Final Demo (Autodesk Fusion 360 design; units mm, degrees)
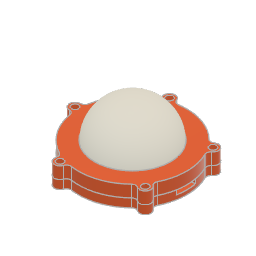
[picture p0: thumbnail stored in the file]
sketch "Sketch1" plane through (0, 0, 0) normal (0, 1, 0) x axis (1, 0, 0)
  line L1 (0, 45) -> (0, 0)
  line L2 (0, -35) -> (0, 0)
  circle C1 centre (0, 0) radius 15
  circle C2 centre (0, 0) radius 17.5
  circle C3 centre (0, 0) radius 22.5
  point P1 (0, 0)
  point P2 (0, 0)
  point P4 (0, 0)
  point P6 (0, 0)
  coincident P1 P2
  concentric C1 C2
  coincident P1 P4
  vertical L1
  coincident P2 P6
  parallel L1 L2
  concentric C2 C3
  dimension "d1" diameter C1 = 30
  dimension "d2" diameter C2 = 35
  dimension "d4" diameter C3 = 45
revolve "Revolve1" sketch "Sketch1" AlongAngle 180 bodies "Membrane"
extrude "Extrude1" add blind -5
move "Move1"
sketch "Sketch2" plane through (0, 0, 0) normal (0, 1, 0) x axis (1, 0, 0)
  line L1 (25, 25) -> (-25, 25)
  line L2 (25, -25) -> (25, 25)
  line L3 (-25, -25) -> (25, -25)
  line L4 (-25, 25) -> (-25, -25)
  circle C1 centre (0, 0) radius 22.5
  point P1 (0, 0)
  point P2 (0, 0)
  coincident P1 P2
  horizontal L1
  vertical L2
  horizontal L3
  vertical L4
  dimension "d7" diameter C1 = 45
extrude "Extrude2" new body sketch "Sketch2" along normal blind 3.5 bodies "Cap"
sketch "Sketch3" plane through (0, 3.5, 0) normal (0, 1, 0) x axis (-1, 0, 0)
  line L1 (-25, 25) -> (25, 25)
  line L2 (-25, -25) -> (-25, 25)
  line L3 (25, -25) -> (-25, -25)
  line L4 (25, 25) -> (25, -25)
  circle C1 centre (0, 0) radius 22.5
  circle C2 centre (0, 0) radius 17.5
  concentric C1 C2
  dimension "d10" diameter C2 = 35
extrude "Extrude3" add sketch "Sketch3" along normal blind 2
extrude "Extrude4" new body sketch "Sketch2" against normal blind 8
sketch "Sketch4" plane through (0, 0, 0) normal (0, 1, 0) x axis (-1, 0, 0)
  line L1 (-25, 25) -> (25, 25)
  line L2 (-25, -25) -> (-25, 25)
  line L3 (25, -25) -> (-25, -25)
  line L4 (25, 25) -> (25, -25)
  line L5 (-6, -0.9751) -> (-25, -0.9751)
  line L6 (0, 1.0068) -> (0, -0.9751)
  line L7 (-25, 1.0068) -> (-6, 1.0068)
  line L8 (0, 8) -> (0, 0)
  line L9 (5.4, 8) -> (-6, 8)
  line L10 (5.4, -8) -> (5.4, 8)
  line L11 (-6, -8) -> (5.4, -8)
  line L12 (-6, -0.9751) -> (-6, -8)
  line L13 (-6, 8) -> (-6, 1.0068)
  circle C1 centre (0, 0) radius 17.5
  circle C2 centre (0, 0) radius 20
  point P6 (-25, -0.9751)
  point P9 (-25, 1.0068)
  point P1 (0, 0)
  point P10 (0, 0)
  point P16 (-6, 1.0068)
  point P18 (0, 0)
  point P19 (0, 0)
  point P11 (0, 8)
  point P12 (-6, 8)
  point P13 (5.4, 8)
  coincident L2 P6
  perpendicular L2 L5
  perpendicular L5 L6
  coincident L2 P9
  perpendicular L2 L7
  coincident P1 P10
  parallel L6 L8
  horizontal L9
  vertical L10
  horizontal L11
  vertical L12
  coincident P16 L12
  collinear L12 L13
  coincident P1 P18
  coincident P10 P19
  dimension "d17" distance P10 P11 = 8
  dimension "d18" distance P12 P13 = 11.4
  dimension "d19" distance L2 L13 = 19
  dimension "d20" diameter C1 = 35
  dimension "d23" diameter C2 = 40
extrude "Extrude6" cut sketch "Sketch4" profile of L2 L5 L7 L9 L10 L11 L13 C1 C2 against normal blind 1
sketch "Sketch5" plane through (0, 5.5, 0) normal (0, 1, 0) x axis (-1, 0, 0)
  line L1 (25, 25) -> (25, -25)
  line L2 (-25, 25) -> (25, 25)
  line L3 (-25, -25) -> (-25, 25)
  line L4 (25, -25) -> (-25, -25)
  line L5 (-25, 25) -> (25, -25)
  line L6 (25, 25) -> (-25, -25)
  line L7 (-20, -20) -> (20, -20)
  line L8 (-20, 20) -> (-20, -20)
  line L9 (20, 20) -> (-20, 20)
  line L10 (20, -20) -> (20, 20)
  circle C1 centre (0, 0) radius 17.5
  point P3 (25, -25)
  point P7 (25, -25)
  point P5 (-25, 25)
  point P8 (-25, 25)
  point P6 (-25, -25)
  point P9 (-25, -25)
  point P4 (25, 25)
  point P10 (25, 25)
  point P13 (-20, 20)
  point P11 (20, -20)
  coincident P3 P7
  coincident P5 P8
  coincident P6 P9
  coincident P4 P10
  horizontal L7
  vertical L8
  horizontal L9
  vertical L10
  coincident L5 P13
  coincident L5 P11
sketch "Sketch6" plane through (0, -8, 0) normal (0, -1, 0) x axis (1, 0, 0)
  line L1 (-25, 25) -> (25, 25)
  line L2 (-25, -25) -> (-25, 25)
  line L3 (25, -25) -> (-25, -25)
  line L4 (25, 25) -> (25, -25)
  line L5 (-18.35, 22.6847) -> (-16.8, 20)
  line L6 (-21.45, 22.6847) -> (-18.35, 22.6847)
  line L7 (-23, 20) -> (-21.45, 22.6847)
  line L8 (-21.45, 17.3153) -> (-23, 20)
  line L9 (-18.35, 17.3153) -> (-21.45, 17.3153)
  line L10 (-16.8, 20) -> (-18.35, 17.3153)
  line L11 (21.65, 22.6847) -> (23.2, 20)
  line L12 (18.55, 22.6847) -> (21.65, 22.6847)
  line L13 (17, 20) -> (18.55, 22.6847)
  line L14 (18.55, 17.3153) -> (17, 20)
  line L15 (21.65, 17.3153) -> (18.55, 17.3153)
  line L16 (23.2, 20) -> (21.65, 17.3153)
  line L17 (-22.6847, -18.45) -> (-20, -16.9)
  line L18 (-22.6847, -21.55) -> (-22.6847, -18.45)
  line L19 (-20, -23.1) -> (-22.6847, -21.55)
  line L20 (-17.3153, -21.55) -> (-20, -23.1)
  line L21 (-17.3153, -18.45) -> (-17.3153, -21.55)
  line L22 (-20, -16.9) -> (-17.3153, -18.45)
  line L23 (17.3153, -18.45) -> (20, -16.9)
  line L24 (17.3153, -21.55) -> (17.3153, -18.45)
  line L25 (20, -23.1) -> (17.3153, -21.55)
  line L26 (22.6847, -21.55) -> (20, -23.1)
  line L27 (22.6847, -18.45) -> (22.6847, -21.55)
  line L28 (20, -16.9) -> (22.6847, -18.45)
  point P6 (-16.8, 20)
  point P12 (-19.9, 20)
  point P13 (23.2, 20)
  point P19 (20.1, 20)
  point P20 (-20, -16.9)
  point P26 (-20, -20)
  point P27 (20, -16.9)
  point P33 (20, -20)
  dimension "d24" distance P6 P12 = 3.1
  dimension "d25" distance P13 P19 = 3.1
  dimension "d26" distance P20 P26 = 3.1
  dimension "d27" distance P27 P33 = 3.1
extrude "Extrude7" cut sketch "Sketch6" profile of L5 L6 L7 L8 L9 L10 L11 L12 L13 L14 L15 L16 L17 L18 L19 L20 L21 L22 L23 L24 L25 L26 L27 L28 against normal blind 2.8
hole "Hole1" HoleDepth 12 HoleDiameter 3.2 TipAngle 180
extrude "Extrude8" cut sketch "Sketch4" profile of L5 L7 C1 C2 against normal blind 0.5
sketch "Sketch7" plane through (0, 0, 0) normal (0, 1, 0) x axis (1, 0, 0)
  line L1 (25, 25) -> (-25, 25)
  line L2 (25, -25) -> (25, 25)
  line L3 (-25, -25) -> (25, -25)
  line L4 (-25, 25) -> (-25, -25)
  horizontal L1
  vertical L2
  horizontal L3
  vertical L4
combine "Combine1"
sketch "Sketch8" plane through (0, 0, 0) normal (0, -1, 0) x axis (1, 0, 0)
  line L1 (25, 25) -> (-25, 25)
  line L2 (25, -25) -> (25, 25)
  line L3 (-25, -25) -> (25, -25)
  line L4 (-25, 25) -> (-25, -25)
  circle C1 centre (0, 0) radius 15
  circle C2 centre (0, 0) radius 22.5
  circle C3 centre (-0.0783, 18.7498) radius 3.75
  circle C4 centre (-0.0153, -20.25) radius 2.25
  point P1 (0, 0)
  point P7 (0, 0)
  horizontal L1
  vertical L2
  horizontal L3
  vertical L4
  coincident P1 P7
  tangent C1 C3
  dimension "d39" diameter C2 = 45
extrude "Extrude1" add sketch "Sketch8" profile of C1 L1 L2 L3 L4 along normal blind 5
extrude "Extrude2" cut sketch "Sketch8" profile of C2 C3 C4 along normal blind 10
sketch "Sketch9" plane through (0, -5, 0) normal (0, -1, 0) x axis (1, 0, 0)
  line L1 (25, -25) -> (-25, -25)
  line L2 (25, 25) -> (25, -25)
  line L3 (-25, 25) -> (25, 25)
  line L4 (-25, -25) -> (-25, 25)
  line L5 (25, -25) -> (-25, 25)
  line L6 (-25, -25) -> (25, 25)
  line L7 (21, 21) -> (-21, 21)
  line L8 (21, -21) -> (21, 21)
  line L9 (-21, -21) -> (21, -21)
  line L10 (-21, 21) -> (-21, -21)
  circle C1 centre (-0.0783, 18.7498) radius 3.75
  arc A1 centre (0, 0) radius 22.5 clockwise from (-0.0034, -22.5) to (-0.0307, -22.5)
  arc A2 centre (-0.0153, -20.25) radius 2.25 clockwise from (-0.0307, -22.5) to (-0.0034, -22.5)
  circle C2 centre (0, 0) radius 22.5
  point P1 (0, 0)
  point P11 (0, 0)
  point P10 (-25, 25)
  point P12 (-25, 25)
  point P8 (25, -25)
  point P13 (25, -25)
  point P9 (25, 25)
  point P14 (25, 25)
  point P7 (-25, -25)
  point P15 (-25, -25)
  point P18 (21, -21)
  point P16 (-21, 21)
  coincident P1 P11
  tangent C1 C2
  coincident P10 P12
  coincident P8 P13
  coincident P9 P14
  coincident P7 P15
  horizontal L7
  vertical L8
  horizontal L9
  vertical L10
  coincident L5 P18
  coincident L5 P16
hole "Hole1" HoleDepth 31 HoleDiameter 3.2 TipAngle 180
sketch "Sketch10" plane through (0, 25, 0) normal (0, 1, 0) x axis (-1, 0, 0)
  line L1 (-25, 25) -> (25, 25)
  line L2 (-25, -25) -> (-25, 25)
  line L3 (25, -25) -> (-25, -25)
  line L4 (25, 25) -> (25, -25)
  line L5 (23.6847, -22.55) -> (21, -24.1)
  line L6 (23.6847, -19.45) -> (23.6847, -22.55)
  line L7 (21, -17.9) -> (23.6847, -19.45)
  line L8 (18.3153, -19.45) -> (21, -17.9)
  line L9 (18.3153, -22.55) -> (18.3153, -19.45)
  line L10 (21, -24.1) -> (18.3153, -22.55)
  line L11 (-18.3153, -22.55) -> (-21, -24.1)
  line L12 (-18.3153, -19.45) -> (-18.3153, -22.55)
  line L13 (-21, -17.9) -> (-18.3153, -19.45)
  line L14 (-23.6847, -19.45) -> (-21, -17.9)
  line L15 (-23.6847, -22.55) -> (-23.6847, -19.45)
  line L16 (-21, -24.1) -> (-23.6847, -22.55)
  line L17 (-18.3153, 19.45) -> (-21, 17.9)
  line L18 (-18.3153, 22.55) -> (-18.3153, 19.45)
  line L19 (-21, 24.1) -> (-18.3153, 22.55)
  line L20 (-23.6847, 22.55) -> (-21, 24.1)
  line L21 (-23.6847, 19.45) -> (-23.6847, 22.55)
  line L22 (-21, 17.9) -> (-23.6847, 19.45)
  line L23 (23.6847, 19.45) -> (21, 17.9)
  line L24 (23.6847, 22.55) -> (23.6847, 19.45)
  line L25 (21, 24.1) -> (23.6847, 22.55)
  line L26 (18.3153, 22.55) -> (21, 24.1)
  line L27 (18.3153, 19.45) -> (18.3153, 22.55)
  line L28 (21, 17.9) -> (18.3153, 19.45)
  circle C1 centre (-21, -21) radius 1.6
  circle C2 centre (21, 21) radius 1.6
  circle C3 centre (-21, 21) radius 1.6
  circle C4 centre (21, -21) radius 1.6
  point P5 (21, -21)
  point P16 (21, -21)
  point P2 (-21, -21)
  point P23 (-21, -21)
  point P4 (-21, 21)
  point P30 (-21, 21)
  point P3 (21, 21)
  point P37 (21, 21)
  point P10 (21, -24.1)
  point P17 (-21, -24.1)
  point P24 (-21, 17.9)
  point P31 (21, 17.9)
  coincident P5 P16
  coincident P2 P23
  coincident P4 P30
  coincident P3 P37
  dimension "d45" distance P10 P16 = 3.1
  dimension "d46" distance P17 P23 = 3.1
  dimension "d47" distance P24 P30 = 3.1
  dimension "d48" distance P31 P37 = 3.1
extrude "Extrude3" cut sketch "Sketch10" profile of C1 C2 C3 C4 L5 L6 L7 L8 L9 L10 L11 L12 L13 L14 L15 L16 L17 L18 L19 L20 L21 L22 L23 L24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 against normal blind 3
extrude "Extrude9" cut of existing geometry blind -1
sketch "Sketch11" plane through (0, -2, 0) normal (0, 1, 0) x axis (-1, 0, 0)
  line L1 (-25, 1.0068) -> (-17.471, 1.0068)
  line L2 (-25, -0.9751) -> (-25, 1.0068)
  line L3 (-17.4728, -0.9751) -> (-25, -0.9751)
  line L4 (-16.4984, 3) -> (-25.5767, 3)
  line L5 (-16.4984, -3.0369) -> (-16.4984, 3)
  line L6 (-25.5767, -3.0369) -> (-16.4984, -3.0369)
  line L7 (-25.5767, 3) -> (-25.5767, -3.0369)
  arc A1 centre (0, 0) radius 17.5 clockwise from (-17.471, 1.0068) to (-17.4728, -0.9751)
  horizontal L4
  vertical L5
  horizontal L6
  vertical L7
extrude "Extrude10" cut sketch "Sketch11" along normal blind 3
extrude "Extrude11" cut of existing geometry blind -4
extrude "Extrude12" cut of existing geometry blind -5
sketch "Sketch12" plane through (0, -2, 0) normal (0, 1, 0) x axis (-1, 0, 0)
  line L1 (-25, 3) -> (-17.2409, 3)
  line L2 (-25, -3.0369) -> (-25, 3)
  line L3 (-17.2345, -3.0369) -> (-25, -3.0369)
  line L4 (-16, 3) -> (-17.2409, 3)
  line L5 (-15.993, -3.0369) -> (-17.2345, -3.0369)
  arc A1 centre (0, 0) radius 17.5 clockwise from (-17.2409, 3) to (-17.2345, -3.0369)
  circle C1 centre (0, 0) radius 16.2788
  point P2 (-17.2409, 3)
  point P8 (-17.2409, 3)
  point P9 (-16, 3)
  point P5 (-17.2345, -3.0369)
  point P10 (-17.2345, -3.0369)
  point P11 (-15.993, -3.0369)
  concentric A1 C1
  coincident P2 P8
  coincident C1 P9
  parallel L1 L4
  coincident P5 P10
  coincident C1 P11
  parallel L3 L5
extrude "Extrude13" add sketch "Sketch12" profile of A1 C1 L4 L5 along normal blind 1
offset_faces "OffsetFaces1" distance -1
extrude "Extrude14" add of existing geometry blind 0.5
extrude "Extrude15" add of existing geometry blind 0.5
offset_faces "OffsetFaces2" distance 1
sketch "Sketch13" plane through (0, 5.5, 0) normal (0, 1, 0) x axis (-1, 0, 0)
  line L1 (25, 25) -> (25, -25)
  line L2 (-25, 25) -> (25, 25)
  line L3 (-25, -25) -> (-25, 25)
  line L4 (25, -25) -> (-25, -25)
  circle C1 centre (-20, 20) radius 1.6
  circle C2 centre (20, -20) radius 1.6
  circle C3 centre (-20, -20) radius 1.6
  circle C4 centre (20, 20) radius 1.6
  circle C5 centre (0, 0) radius 17.5
  circle C6 centre (0, 0) radius 22.5
  circle C7 centre (0, 0) radius 25
  point P1 (0, 0)
  point P11 (0, 0)
  coincident P1 P11
  concentric C5 C7
  tangent L2 C7
  dimension "d67" diameter C6 = 45
extrude "Extrude16" cut sketch "Sketch13" profile of C1 C2 C3 C4 L1 L2 L3 L4 C7 against normal blind 23
sketch "Sketch14" plane through (0, 0, 0) normal (0, 1, 0) x axis (1, 0, 0)
  line L1 (-26.6053, 2.6) -> (-26.6, 2.6)
  line L2 (-26.6053, -2.6) -> (-26.6, -2.6)
  circle C1 centre (-26.6, 0) radius 1.6
  arc A1 centre (-26.6053, 4.6) radius 2 clockwise from (-24.6345, 4.2593) to (-26.6053, 2.6)
  arc A2 centre (-26.6053, -4.6) radius 2 clockwise from (-26.6053, -2.6) to (-24.6345, -4.2593)
  arc A3 centre (-26.6, 0) radius 2.6 clockwise from (-26.6, -2.6) to (-26.6, 2.6)
  arc A4 centre (-3.8466, -26.7246) radius 2 clockwise from (-5.7487, -26.1066) to (-3.5617, -24.745)
  arc A5 centre (-8.2199, -25.2981) radius 2.6 clockwise from (-5.7471, -26.1015) to (-10.6926, -24.4947)
  circle C2 centre (-8.2199, -25.2981) radius 1.6
  arc A6 centre (-12.5963, -23.8816) radius 2 clockwise from (-11.6633, -22.1126) to (-10.6942, -24.4997)
  arc A7 centre (24.2279, -11.9167) radius 2 clockwise from (23.0524, -13.5347) to (22.4333, -11.034)
  arc A8 centre (21.5199, -15.6351) radius 2.6 clockwise from (23.0481, -13.5316) to (19.9916, -17.7385)
  circle C3 centre (21.5199, -15.6351) radius 1.6
  arc A9 centre (18.8203, -19.3597) radius 2 clockwise from (17.4262, -17.9256) to (19.9959, -17.7416)
  arc A10 centre (18.8203, 19.3597) radius 2 clockwise from (19.9959, 17.7416) to (17.4262, 17.9256)
  arc A11 centre (21.5199, 15.6351) radius 2.6 clockwise from (19.9916, 17.7385) to (23.0481, 13.5316)
  circle C4 centre (21.5199, 15.6351) radius 1.6
  arc A12 centre (24.2279, 11.9167) radius 2 clockwise from (22.4333, 11.034) to (23.0524, 13.5347)
  arc A13 centre (-12.5963, 23.8816) radius 2 clockwise from (-10.6942, 24.4997) to (-11.6633, 22.1126)
  arc A14 centre (-8.2199, 25.2981) radius 2.6 clockwise from (-10.6926, 24.4947) to (-5.7471, 26.1015)
  circle C5 centre (-8.2199, 25.2981) radius 1.6
  arc A15 centre (-3.8466, 26.7246) radius 2 clockwise from (-3.5617, 24.745) to (-5.7487, 26.1066)
  arc A16 centre (0, 0) radius 25 clockwise from (-11.6633, -22.1126) to (-24.6345, -4.2593)
  arc A17 centre (0, 0) radius 25 clockwise from (-11.6633, -22.1126) to (-24.6345, -4.2593)
  arc A18 centre (0, 0) radius 25 clockwise from (17.4262, -17.9256) to (-3.5617, -24.745)
  arc A19 centre (0, 0) radius 25 clockwise from (17.4262, -17.9256) to (-3.5617, -24.745)
  arc A20 centre (0, 0) radius 25 clockwise from (22.4333, 11.034) to (22.4333, -11.034)
  arc A21 centre (0, 0) radius 25 clockwise from (22.4333, 11.034) to (22.4333, -11.034)
  arc A22 centre (0, 0) radius 25 clockwise from (-3.5617, 24.745) to (17.4262, 17.9256)
  arc A23 centre (0, 0) radius 25 clockwise from (-24.6345, 4.2593) to (-11.6633, 22.1126)
  arc A24 centre (0, 0) radius 25 clockwise from (-3.5617, 24.745) to (20.2254, 14.6946)
  arc A25 centre (0, 0) radius 25 clockwise from (-24.6345, 4.2593) to (-11.6633, 22.1126)
  circle C6 centre (0, 0) radius 22.5
  point P58 (20.2254, 14.6946)
  concentric C1 A3
  tangent L1 A3
  horizontal L1
  tangent L1 A1
  horizontal L2
  tangent L2 A2
  tangent A2 A17
  concentric A16 A18
  concentric A17 A19
  concentric A18 A21
  concentric A19 A20
  coincident C4 P58
  concentric A20 A22
  concentric A21 A24
  concentric A22 A23
  concentric A24 A25
  concentric A16 C6
  dimension "d71" diameter A3 = 5.2 (= "3.2 mm + 2 mm")
  dimension "d72" radius A1 = 2
  dimension "d73" radius A2 = 2
  dimension "d75" C-Pattern1-Angle = 360
extrude "Extrude17" add sketch "Sketch14" profile of A23 C1 A3 L1 A1 L2 A2 A4 A5 C2 A6 A7 A8 C3 A9 A10 A11 C4 A12 A13 A14 C5 A15 A25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 along normal blind 5.5
extrude "Extrude18" add sketch "Sketch14" profile of A23 C1 A3 L1 A1 L2 A2 A4 A5 C2 A6 A7 A8 C3 A9 A10 A11 C4 A12 A13 A14 C5 A15 A25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 against normal blind 3
sketch "Sketch15" plane through (0, 0, 0) normal (0, 1, 0) x axis (-1, 0, 0)
  line L1 (-14.9814, 3) -> (-22.2991, 3)
  line L2 (-22.2941, -3.0369) -> (-14.974, -3.0369)
  line L3 (-26.3152, 3) -> (-21.5, 3)
  line L4 (-26.5, -3.0369) -> (-21.801, -3.0369)
  arc A1 centre (0, 0) radius 25 clockwise from (-17.4262, 17.9256) to (3.5617, 24.745)
  arc A2 centre (-18.8203, 19.3597) radius 2 clockwise from (-17.4262, 17.9256) to (-19.9959, 17.7416)
  arc A3 centre (-21.5199, 15.6351) radius 2.6 clockwise from (-23.0481, 13.5316) to (-19.9959, 17.7416)
  arc A4 centre (-24.2279, 11.9167) radius 2 clockwise from (-23.0481, 13.5316) to (-22.4333, 11.034)
  arc A5 centre (0, 0) radius 25 clockwise from (-22.4333, -11.034) to (-22.4333, 11.034)
  arc A6 centre (-24.2279, -11.9167) radius 2 clockwise from (-22.4333, -11.034) to (-23.0524, -13.5347)
  arc A7 centre (-21.5199, -15.6351) radius 2.6 clockwise from (-19.9916, -17.7385) to (-23.0524, -13.5347)
  arc A8 centre (-18.8203, -19.3597) radius 2 clockwise from (-19.9916, -17.7385) to (-17.4262, -17.9256)
  arc A9 centre (0, 0) radius 25 clockwise from (3.5617, -24.745) to (-17.4262, -17.9256)
  arc A10 centre (3.8466, -26.7246) radius 2 clockwise from (3.5617, -24.745) to (5.7487, -26.1066)
  arc A11 centre (8.2199, -25.2981) radius 2.6 clockwise from (10.6926, -24.4947) to (5.7487, -26.1066)
  arc A12 centre (12.5963, -23.8816) radius 2 clockwise from (10.6926, -24.4947) to (11.6633, -22.1126)
  arc A13 centre (0, 0) radius 25 clockwise from (24.6345, -4.2593) to (11.6633, -22.1126)
  arc A14 centre (26.6053, -4.6) radius 2 clockwise from (24.6345, -4.2593) to (26.6, -2.6)
  arc A15 centre (26.6, 0) radius 2.6 clockwise from (26.6, 2.6) to (26.6, -2.6)
  arc A16 centre (26.6053, 4.6) radius 2 clockwise from (26.6, 2.6) to (24.6345, 4.2593)
  arc A17 centre (0, 0) radius 25 clockwise from (11.6633, 22.1126) to (24.6345, 4.2593)
  arc A18 centre (12.5963, 23.8816) radius 2 clockwise from (11.6633, 22.1126) to (10.6942, 24.4997)
  arc A19 centre (8.2199, 25.2981) radius 2.6 clockwise from (5.7471, 26.1015) to (10.6942, 24.4997)
  arc A20 centre (3.8466, 26.7246) radius 2 clockwise from (5.7471, 26.1015) to (3.5617, 24.745)
  circle C1 centre (-21.5199, 15.6351) radius 1.6
  arc A21 centre (0, 0) radius 15.2788 clockwise from (-14.9814, 3) to (-14.974, -3.0369)
  arc A22 centre (0, 0) radius 22.5 clockwise from (-22.2941, -3.0369) to (-22.2991, 3)
  circle C2 centre (8.2199, 25.2981) radius 1.6
  circle C3 centre (26.6, 0) radius 1.6
  circle C4 centre (-21.5199, -15.6351) radius 1.6
  circle C5 centre (8.2199, -25.2981) radius 1.6
  point P42 (-21.5, 3)
  point P44 (-21.801, -3.0369)
  coincident L1 P42
  coincident L2 P44
  parallel L2 L4
extrude "Extrude19" cut sketch "Sketch15" profile of A5 A22 L3 L4 to an object
extrude "Extrude20" add of existing geometry blind 1
sketch "Sketch16" plane through (0, 0, 0) normal (0, 1, 0) x axis (1, 0, 0)
  line L1 (72.6111, 30) -> (0, 30)
  line L2 (108.6611, 4.0167) -> (109.6686, 0.9941)
  line L3 (105.2381, -6.3492) -> (109.3713, -0.8383)
  line L4 (95.4303, -1.1442) -> (102.3887, -6.711)
  line L5 (87.7388, -6.5539) -> (92.7347, -1.3244)
  line L6 (79.4294, -1.3816) -> (84.9111, -6.6184)
  line L7 (72.3176, -5.9305) -> (76.6017, -1.4461)
  line L8 (63.4306, -1.1469) -> (69.6205, -6.1094)
  line L9 (56.6131, -5.6387) -> (60.7334, -1.3258)
  line L10 (50.283, -1.5343) -> (53.6327, -5.5401)
  line L11 (42.8003, -5.1843) -> (47.4657, -1.283)
  line L12 (35, 0) -> (40.1085, -5.0696)
  line L13 (35, 0) -> (-30, 0)
  circle C1 centre (0, 0) radius 30
  arc A1 centre (0, 0) radius 25 clockwise from (22.4333, 11.034) to (22.4333, -11.034)
  arc A2 centre (24.2279, 11.9167) radius 2 clockwise from (22.4333, 11.034) to (23.0524, 13.5347)
  arc A3 centre (21.5199, 15.6351) radius 2.6 clockwise from (19.9916, 17.7385) to (23.0524, 13.5347)
  arc A4 centre (18.8203, 19.3597) radius 2 clockwise from (19.9916, 17.7385) to (17.4262, 17.9256)
  arc A5 centre (0, 0) radius 25 clockwise from (-3.5617, 24.745) to (17.4262, 17.9256)
  arc A6 centre (-3.8466, 26.7246) radius 2 clockwise from (-3.5617, 24.745) to (-5.7487, 26.1066)
  arc A7 centre (-8.2199, 25.2981) radius 2.6 clockwise from (-10.6926, 24.4947) to (-5.7487, 26.1066)
  arc A8 centre (-12.5963, 23.8816) radius 2 clockwise from (-10.6926, 24.4947) to (-11.6633, 22.1126)
  arc A9 centre (0, 0) radius 25 clockwise from (-24.6345, 4.2593) to (-11.6633, 22.1126)
  arc A10 centre (-26.6053, 4.6) radius 2 clockwise from (-24.6345, 4.2593) to (-26.6, 2.6)
  arc A11 centre (-26.6, 0) radius 2.6 clockwise from (-26.6, -2.6) to (-26.6, 2.6)
  arc A12 centre (-26.6053, -4.6) radius 2 clockwise from (-26.6, -2.6) to (-24.6345, -4.2593)
  arc A13 centre (0, 0) radius 25 clockwise from (-11.6633, -22.1126) to (-24.6345, -4.2593)
  arc A14 centre (-12.5963, -23.8816) radius 2 clockwise from (-11.6633, -22.1126) to (-10.6942, -24.4997)
  arc A15 centre (-8.2199, -25.2981) radius 2.6 clockwise from (-5.7471, -26.1015) to (-10.6942, -24.4997)
  arc A16 centre (-3.8466, -26.7246) radius 2 clockwise from (-5.7471, -26.1015) to (-3.5617, -24.745)
  arc A17 centre (0, 0) radius 25 clockwise from (17.4262, -17.9256) to (-3.5617, -24.745)
  arc A18 centre (18.8203, -19.3597) radius 2 clockwise from (17.4262, -17.9256) to (19.9959, -17.7416)
  arc A19 centre (21.5199, -15.6351) radius 2.6 clockwise from (23.0481, -13.5316) to (19.9959, -17.7416)
  arc A20 centre (24.2279, -11.9167) radius 2 clockwise from (23.0481, -13.5316) to (22.4333, -11.034)
  circle C2 centre (21.5199, 15.6351) radius 1.6
  circle C3 centre (21.5199, -15.6351) radius 1.6
  circle C4 centre (-8.2199, 25.2981) radius 1.6
  circle C5 centre (-8.2199, -25.2981) radius 1.6
  circle C6 centre (-26.6, 0) radius 1.6
  circle C7 centre (0, 0) radius 17.5
  arc A21 centre (72.6111, -8) radius 38 clockwise from (72.6111, 30) to (108.6611, 4.0167)
  arc A22 centre (41.5173, -3.65) radius 2 clockwise from (42.8003, -5.1843) to (40.1085, -5.0696)
  arc A23 centre (48.7487, -2.8172) radius 2 clockwise from (47.4657, -1.283) to (50.283, -1.5343)
  arc A24 centre (55.167, -4.2571) radius 2 clockwise from (56.6131, -5.6387) to (53.6327, -5.5401)
  arc A25 centre (62.1796, -2.7073) radius 2 clockwise from (60.7334, -1.3258) to (63.4306, -1.1469)
  arc A26 centre (70.8715, -4.5489) radius 2 clockwise from (72.3176, -5.9305) to (69.6205, -6.1094)
  arc A27 centre (78.0479, -2.8277) radius 2 clockwise from (76.6017, -1.4461) to (79.4294, -1.3816)
  arc A28 centre (86.2926, -5.1723) radius 2 clockwise from (87.7388, -6.5539) to (84.9111, -6.6184)
  arc A29 centre (94.1809, -2.7059) radius 2 clockwise from (92.7347, -1.3244) to (95.4303, -1.1442)
  arc A30 centre (103.6381, -5.1492) radius 2 clockwise from (105.2381, -6.3492) to (102.3887, -6.711)
  arc A31 centre (107.7713, 0.3617) radius 2 clockwise from (109.6686, 0.9941) to (109.3713, -0.8383)
  point P1 (0, 0)
  point P2 (0, 0)
  point P39 (0, 30)
  point P41 (-30, 0)
  point P40 (100, 30)
  point P42 (110, 0)
  coincident P1 P2
  coincident C1 P39
  horizontal L1
  coincident C1 P41
  horizontal L13
  perpendicular L5 L6
  perpendicular L6 L7
  parallel L7 L9
  perpendicular L10 L11
  coincident P40 L1
  coincident P40 L2
  tangent L1 A21
  tangent L2 A21
  tangent L11 A22
  tangent L12 A22
  tangent L10 A23
  tangent L11 A23
  equal A22 A23
  tangent L9 A24
  tangent L10 A24
  equal A22 A24
  tangent L8 A25
  tangent L9 A25
  equal A22 A25
  tangent L7 A26
  tangent L8 A26
  equal A22 A26
  tangent L7 A27
  tangent L6 A27
  equal A22 A27
  tangent L5 A28
  tangent L6 A28
  equal A22 A28
  tangent L4 A29
  tangent L5 A29
  equal A22 A29
  tangent L3 A30
  tangent L4 A30
  equal A22 A30
  coincident P42 L2
  coincident P42 L3
  tangent L2 A31
  tangent L3 A31
  equal A22 A31
  dimension "d84" distance P39 P40 = 100
  dimension "d85" distance P41 P42 = 140
  dimension "d86" radius A21 = 38
  dimension "d87" radius A22 = 2
extrude "Extrude21" new body sketch "Sketch16" against normal blind 2
move "Move2"
sketch "Sketch17" plane through (0, -2, 0) normal (0, 1, 0) x axis (-1, 0, 0)
  line L1 (-14.974, -3.0369) -> (-24.8149, -3.0369)
  line L2 (-24.8193, 3) -> (-14.9814, 3)
  line L3 (-13, -4.4369) -> (-19.8944, -4.4369)
  line L4 (-13.2092, 4.4) -> (-19.9004, 4.4)
  line L5 (-13, -4.4369) -> (-13.2092, 4.4)
  line L6 (-28.2709, -4.4369) -> (-19.8944, -4.4369)
  line L7 (-28.2709, 4.4) -> (-28.2709, -4.4369)
  line L8 (-16.5548, 4.4) -> (-28.2709, 4.4)
  line L9 (-28.2709, 4.4) -> (-13.2092, 4.4)
  line L10 (-28.2709, -4.4369) -> (-13, -4.4369)
  arc A1 centre (0, 0) radius 15.2788 clockwise from (-14.9814, 3) to (-14.974, -3.0369)
  arc A2 centre (0, 0) radius 25 clockwise from (-24.8149, -3.0369) to (-24.8193, 3)
  point P13 (-16.5548, 4.4)
  perpendicular L6 L7
  midpoint L4 P13
  perpendicular L7 L9
  perpendicular L7 L10
extrude "Extrude22" cut sketch "Sketch17" profile of L1 A1 L2 A2 L3 L4 L6 L7 L8 L9 L10 along normal blind 5
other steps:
create_component "CreateComponent2"
named bodies: "Membrane", "Cap", "Base"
